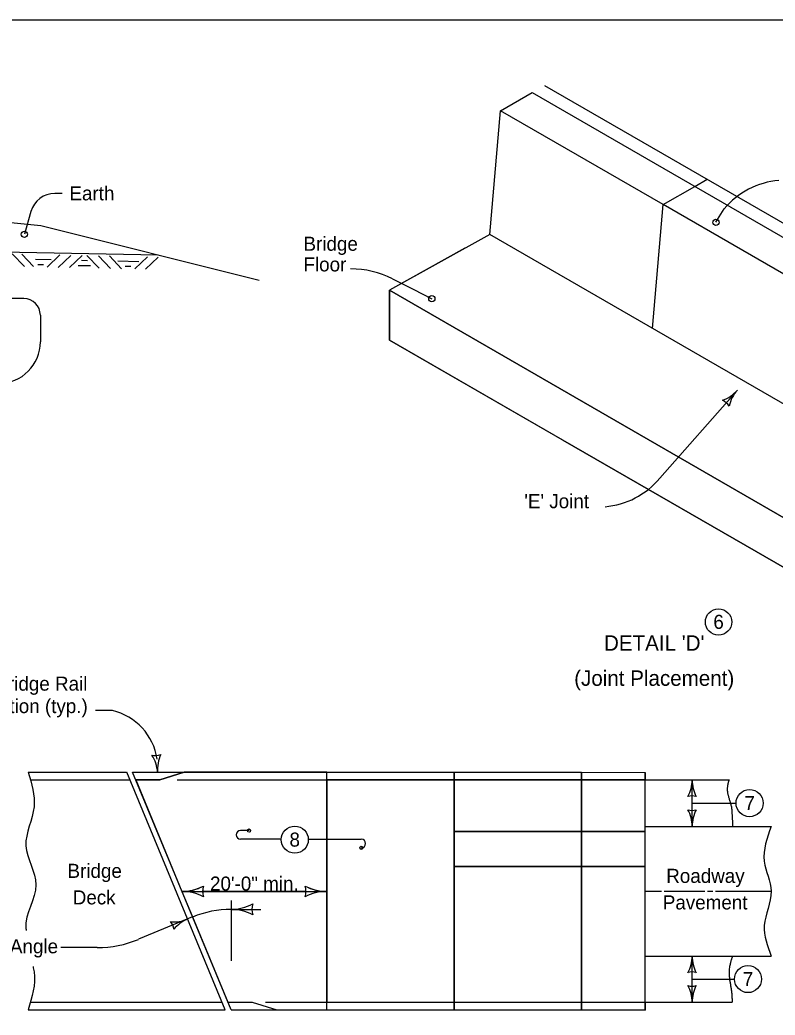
# Model space of a CAD drawing. Extents: x -2134934 to -2124557, y -2139046 to -2134021.
# Drawn here: x -2126647 to -2125788, y -2138168 to -2137036 of the extents above; entities that cross this region are included whole.
import ezdxf

# ---------------------------------------------------------------- set-up
doc = ezdxf.new("R2010")
doc.units = 0
for name, color, linetype in [('BridgeSuperStructureExisting', 7, 'Continuous'), ('dsnAlignmentStation', 7, 'Continuous'), ('dsnCellElements', 7, 'Continuous'), ('dsnStdLabel', 7, 'Continuous'), ('TC_Barrier', 7, 'Continuous')]:
    doc.layers.add(name, color=color, linetype=linetype)

msp = doc.modelspace()

# ---------------------------------------------------------------- linework, layer by layer
at = {"layer": 'BridgeSuperStructureExisting'}
for p, q in [((-2126050, -2137110.4), (-2125548.2, -2137400.1)), ((-2126112.2, -2137280.1), (-2126100, -2137139.2)), ((-2125879.2, -2137225.3), (-2125865, -2137217.2)), ((-2126598.5, -2137233.3), (-2126606.9, -2137233.3)), ((-2126634.2, -2137253.7), (-2126641.7, -2137279.7)), ((-2125927.2, -2137386.9), (-2125915, -2137246)), ((-2125855.1, -2137266.1), (-2125845.8, -2137250.8)), ((-2126735.2, -2137258.5), (-2126622.9, -2137269.7)), ((-2126622.9, -2137269.7), (-2126374.6, -2137331.8)), ((-2126112.2, -2137280.1), (-2126226.3, -2137343.3)), ((-2126112.2, -2137280.1), (-2126226.3, -2137343.3)), ((-2125753.4, -2137487.2), (-2126112.2, -2137280.1)), ((-2125643.5, -2137550.7), (-2126112.2, -2137280.1)), ((-2126140.5, -2137295.7), (-2126226.3, -2137343.3)), ((-2126667.1, -2137299.6), (-2126489.3, -2137303.1)), ((-2126655.4, -2137302.1), (-2126641.5, -2137316.5)), ((-2126644.5, -2137302.4), (-2126631.2, -2137316.4)), ((-2126601.3, -2137303.3), (-2126615.7, -2137317.2)), ((-2126588.9, -2137303.8), (-2126603.3, -2137317.6)), ((-2126575.9, -2137303.8), (-2126590.3, -2137317.7)), ((-2126570.5, -2137303.9), (-2126556.6, -2137318.3)), ((-2126557.5, -2137304.4), (-2126543.6, -2137318.8)), ((-2126545, -2137304.4), (-2126531.2, -2137318.9)), ((-2126501.8, -2137305.3), (-2126516.2, -2137319.2)), ((-2126489.3, -2137305.8), (-2126503.8, -2137319.6)), ((-2126222.9, -2137330.5), (-2126199.6, -2137342.3)), ((-2126226.3, -2137343.3), (-2126226.3, -2137400)), ((-2125775, -2137603.9), (-2126226.3, -2137343.3)), ((-2126226.3, -2137343.3), (-2126226.3, -2137400)), ((-2126226.3, -2137343.3), (-2125775, -2137603.9)), ((-2126226.3, -2137343.3), (-2126029.2, -2137457.2)), ((-2126199.6, -2137342.3), (-2126178.2, -2137353.1)), ((-2126642.4, -2137352.8), (-2126667.1, -2137352.8)), ((-2126623.5, -2137371.7), (-2126623.5, -2137402.1)), ((-2126226.3, -2137400), (-2125757.2, -2137670.8)), ((-2126029.2, -2137513.8), (-2126226.3, -2137400)), ((-2126029.2, -2137457.2), (-2125591.9, -2137709.6)), ((-2125830.6, -2137456.9), (-2125919, -2137557.2)), ((-2126029.2, -2137513.8), (-2125591.9, -2137766.2)), ((-2125591.9, -2137766.2), (-2126029.2, -2137513.8)), ((-2126541.4, -2137821.5), (-2126560.9, -2137821.5)), ((-2126637.5, -2137891.6), (-2126525.4, -2137891.6)), ((-2126413.2, -2138161.9), (-2126525.2, -2137891.6)), ((-2126406.5, -2138161.9), (-2126518.5, -2137891.6)), ((-2126518.5, -2137891.6), (-2126297.8, -2137891.6)), ((-2126459.8, -2137891.6), (-2126487.4, -2137900.3)), ((-2126487.4, -2137900.3), (-2126459.8, -2137891.6)), ((-2126297.8, -2137891.6), (-2126459.8, -2137891.6)), ((-2126297.8, -2137953), (-2126297.8, -2137891.6)), ((-2126297.8, -2138153.1), (-2126297.8, -2137891.6)), ((-2126297.8, -2137891.6), (-2125935.6, -2137891.7)), ((-2126152.9, -2138162), (-2126152.9, -2137891.6)), ((-2126008, -2138162), (-2126008, -2137891.6)), ((-2125935.6, -2138162), (-2125935.6, -2137891.7)), ((-2126634.6, -2137900.3), (-2126521.7, -2137900.3)), ((-2126515, -2137900.3), (-2126487.4, -2137900.3)), ((-2126487.4, -2137900.3), (-2126514.9, -2137900.3)), ((-2126514.9, -2137900.3), (-2126462.4, -2138027.1)), ((-2126467.9, -2137900.3), (-2125840.2, -2137900.3)), ((-2126152.9, -2137900.3), (-2126297.8, -2137900.3)), ((-2125935.6, -2138153.1), (-2125935.6, -2137900.3)), ((-2125882.2, -2137953.1), (-2125882.2, -2137900.3)), ((-2125882.2, -2137926.7), (-2125852.7, -2137926.7)), ((-2125852.7, -2137926.7), (-2125832.2, -2137926.7)), ((-2125935.6, -2137953.1), (-2125792.3, -2137953.1)), ((-2126386.1, -2137957.9), (-2126395.9, -2137957.9)), ((-2126349.4, -2137967.7), (-2126395.9, -2137967.7)), ((-2126318.7, -2137967.7), (-2126258.4, -2137967.7)), ((-2126462.5, -2138027.1), (-2126297.8, -2138027.1)), ((-2126462.4, -2138027.1), (-2126461.8, -2138027.1)), ((-2126438.9, -2138027.1), (-2126321.5, -2138027.1)), ((-2126321.5, -2138027.1), (-2126438.9, -2138027.1)), ((-2126298.6, -2138027.1), (-2126297.8, -2138027.1)), ((-2126297.8, -2138027.1), (-2126297.8, -2138027.1)), ((-2126297.8, -2138027.1), (-2126297.8, -2138095.1)), ((-2126406.5, -2138037.5), (-2126406.5, -2138106.2)), ((-2126450.3, -2138056.2), (-2126511.7, -2138081.6)), ((-2126406.5, -2138047.5), (-2126372.6, -2138047.5)), ((-2126558.8, -2138091), (-2126600.2, -2138091)), ((-2126297.8, -2138095.1), (-2126297.8, -2138153.1)), ((-2126297.8, -2138161.9), (-2126297.8, -2138095.1)), ((-2125935.6, -2138100.6), (-2125792.3, -2138100.6)), ((-2125882.2, -2138153.1), (-2125882.2, -2138100.6)), ((-2125882.2, -2138126.8), (-2125852.7, -2138126.8)), ((-2125852.7, -2138126.8), (-2125834, -2138126.8)), ((-2126634.7, -2138153.1), (-2126416.9, -2138153.1)), ((-2126410.2, -2138153.1), (-2126382.6, -2138153.1)), ((-2126410.2, -2138153.1), (-2126382.6, -2138153.1)), ((-2126382.6, -2138153.1), (-2126354.5, -2138161.9)), ((-2126382.6, -2138153.1), (-2126354.5, -2138161.9)), ((-2126367.5, -2138153.1), (-2125836.6, -2138153.1)), ((-2126297.8, -2138153.1), (-2126247.4, -2138153.1)), ((-2126247.4, -2138153.1), (-2126247.4, -2138153.1)), ((-2126637.5, -2138161.9), (-2126413.2, -2138161.9)), ((-2126406.5, -2138161.9), (-2126297.8, -2138161.9)), ((-2126354.5, -2138161.9), (-2126297.8, -2138161.9)), ((-2126297.8, -2138161.9), (-2125935.6, -2138162))]:
    msp.add_line(p, q, dxfattribs=at)
for points in [[(-2126064.2, -2137118.5), (-2125698.1, -2137329.8), (-2125607.6, -2137382.1), (-2125562.4, -2137408.2), (-2125590.7, -2137424.6), (-2125643.5, -2137402.8), (-2125734, -2137350.5), (-2125915, -2137246), (-2126100, -2137139.2)], [(-2126100, -2137139.2), (-2126064.2, -2137118.5)], [(-2125915, -2137246), (-2125879.2, -2137225.3)], [(-2126629.1, -2137308.2), (-2126611, -2137308.6)], [(-2126576.5, -2137309.3), (-2126570, -2137309.4)], [(-2126535.5, -2137310.1), (-2126511.5, -2137310.6)], [(-2126626.4, -2137314.1), (-2126619.9, -2137314.2)], [(-2126580.5, -2137315.1), (-2126566.3, -2137315.4)], [(-2126526.9, -2137316.1), (-2126520.4, -2137316.2)], [(-2126226.3, -2137400), (-2126226.3, -2137343.3)], [(-2126226.3, -2137400), (-2126226.3, -2137343.3)], [(-2126297.8, -2138027.1), (-2126297.8, -2137967.7), (-2126297.8, -2137953), (-2126297.8, -2137900.3), (-2126297.8, -2137891.6)], [(-2126297.8, -2137900.3), (-2126297.8, -2137967.7), (-2126297.8, -2138027.1)], [(-2126152.9, -2138153.1), (-2126152.9, -2138026.7), (-2126152.9, -2137900.3)], [(-2126462.4, -2138027.1), (-2126450.3, -2138056.2), (-2126410.2, -2138153.1)], [(-2126297.8, -2138161.9), (-2126297.8, -2138153.1), (-2126297.8, -2138100.5), (-2126297.8, -2138027.1)], [(-2126297.8, -2138027.1), (-2126297.8, -2138027.1)], [(-2125935.6, -2138026.8), (-2125916.9, -2138026.8)], [(-2125913.8, -2138026.8), (-2125867.7, -2138026.8)], [(-2125864.7, -2138026.8), (-2125858.5, -2138026.8)], [(-2125855.4, -2138026.8), (-2125792.3, -2138026.8)], [(-2126247.4, -2138153.1), (-2126199.7, -2138153.1), (-2126152.9, -2138153.1)]]:
    msp.add_lwpolyline(points, dxfattribs=at)
for centre, radius in [((-2125852.1, -2137720.7), 15), ((-2125816.8, -2137926.7), 15.4), ((-2126334.1, -2137968.2), 15.4), ((-2126334.1, -2137968.2), 15.4), ((-2125818.6, -2138126.8), 15.4)]:
    msp.add_circle(centre, radius, dxfattribs=at)
for centre, radius, start, end in [((-2125775.9, -2137309.2), 91, 94.8409, 140.1467), ((-2126606.9, -2137261.7), 28.4, 90, 163.739), ((-2126270.6, -2137425), 105.9, 63.2177, 90), ((-2126642.4, -2137371.7), 18.9, 0, 90), ((-2126670.8, -2137402.1), 47.3, 270, 360), ((-2125988.9, -2137498.9), 91, 274.8409, 320.1467), ((-2126556.6, -2137886.4), 66.7, 8.4828, 76.8823), ((-2125922.4, -2137900.3), 40.2, 331.9275, 360), ((-2125842, -2137900.3), 40.2, 180, 208.0725), ((-2125882.2, -2137934), 15.5, 72.2666, 107.7334), ((-2125882.2, -2137919.4), 15.5, 252.2666, 287.7333), ((-2125922.4, -2137953.1), 40.2, 360, 28.0725), ((-2125842, -2137953.1), 40.2, 151.9275, 180), ((-2126395.9, -2137962.8), 4.92, 90, 270), ((-2126258.4, -2137972.7), 4.92, 270, 90), ((-2126462.5, -2137974.9), 52.2, 270, 298.0725), ((-2126462.5, -2137974.9), 52.2, 270.8433, 298.0725), ((-2126418.7, -2138027.1), 20.2, 162.2666, 179.9839), ((-2126418.7, -2138027.1), 20.2, 162.2666, 197.7334), ((-2126341.6, -2138027.1), 20.2, 0.0161, 17.7334), ((-2126297.8, -2137974.9), 52.2, 241.9275, 269.1567), ((-2126341.6, -2138027.1), 20.2, 342.2666, 17.7334), ((-2126297.8, -2137974.9), 52.2, 241.9275, 270), ((-2126462.5, -2138079.4), 52.2, 61.9275, 90), ((-2126462.5, -2138079.4), 52.2, 61.9275, 89.8364), ((-2126418.7, -2138027.1), 20.2, 179.9839, 197.7334), ((-2126297.8, -2138079.4), 52.2, 90.0176, 118.0725), ((-2126341.6, -2138027.1), 20.2, 342.2666, 0.0161), ((-2126297.8, -2138079.4), 52.2, 90, 118.0725), ((-2126297.8, -2137974.9), 52.2, 269.9824, 270), ((-2126406.5, -2137995.3), 52.2, 270, 298.0725), ((-2126406.5, -2137995.3), 52.2, 270, 298.0725), ((-2126362.7, -2138047.5), 20.2, 162.2666, 197.7334), ((-2126362.7, -2138047.5), 20.2, 162.2666, 197.7334), ((-2126406.5, -2138162), 114.5, 90, 112.5), ((-2126406.5, -2138099.7), 52.2, 61.9275, 90), ((-2126406.5, -2138099.7), 52.2, 61.9275, 90), ((-2126471.4, -2138021.5), 40.2, 264.4275, 292.5), ((-2126487.1, -2138071.5), 15.5, 4.7666, 40.2333), ((-2126440.6, -2138095.7), 40.2, 112.5, 140.5725), ((-2126558.8, -2137968.1), 122.9, 270, 292.5), ((-2125922.4, -2138100.6), 40.2, 331.9275, 360), ((-2125842, -2138100.6), 40.2, 180, 208.0725), ((-2125882.2, -2138134.2), 15.5, 72.2666, 107.7334), ((-2125882.2, -2138119.5), 15.5, 252.2666, 287.7333), ((-2125922.4, -2138153.1), 40.2, 360, 28.0725), ((-2125842, -2138153.1), 40.2, 151.9275, 180), ((-2126287.5, -2138153.1), 40.2, 359.9859, 360)]:
    msp.add_arc(centre, radius, start, end, dxfattribs=at)
for points in [[(-2126637.5, -2137891.6), (-2126630.6, -2137930.8), (-2126639.9, -2137975.2), (-2126628.5, -2138019.5), (-2126639.9, -2138069.1), (-2126639.6, -2138071.4)], [(-2125792.3, -2137953.1), (-2125800.1, -2137992.8), (-2125792.3, -2138026.9), (-2125800.1, -2138066), (-2125792.3, -2138100.6)], [(-2126631.8, -2138112.4), (-2126630.6, -2138118.6), (-2126637.5, -2138161.9)]]:
    msp.add_spline(points, degree=3, dxfattribs=at)
for points in [[(-2125840.2, -2137900.3), (-2125840.4, -2137900.8), (-2125840.6, -2137901.3), (-2125840.7, -2137901.8), (-2125840.9, -2137902.3), (-2125841, -2137902.8), (-2125841.2, -2137903.3), (-2125841.4, -2137904.3), (-2125841.6, -2137905.2), (-2125841.8, -2137906.3), (-2125842, -2137907.2), (-2125842.1, -2137908.2), (-2125842.1, -2137909.2), (-2125842.2, -2137909.7), (-2125842.2, -2137910.2), (-2125842.2, -2137910.7), (-2125842.2, -2137911.2), (-2125842.2, -2137911.7), (-2125842.2, -2137912.2), (-2125842.1, -2137913.2), (-2125842, -2137914.1), (-2125841.8, -2137915.1), (-2125841.7, -2137916), (-2125841.5, -2137917), (-2125841.2, -2137917.9), (-2125840.7, -2137919.8), (-2125840.1, -2137921.6), (-2125839.6, -2137923.5), (-2125839, -2137925.4), (-2125838.5, -2137927.3), (-2125837.9, -2137929.2), (-2125837.6, -2137930.1), (-2125837.5, -2137931.1), (-2125837.3, -2137932.1), (-2125837.2, -2137933), (-2125837, -2137934), (-2125837, -2137934.9), (-2125836.9, -2137936.5), (-2125836.8, -2137938), (-2125836.8, -2137939.5), (-2125836.7, -2137941), (-2125836.6, -2137942.5), (-2125836.5, -2137944), (-2125836.4, -2137945.5), (-2125836.4, -2137947), (-2125836.3, -2137948.5), (-2125836.3, -2137950), (-2125836.2, -2137951.5), (-2125836.2, -2137953.1)], [(-2125836.2, -2138100.6), (-2125836.5, -2138101.4), (-2125836.8, -2138102.3), (-2125837.1, -2138103.2), (-2125837.3, -2138104.1), (-2125837.6, -2138104.9), (-2125837.9, -2138105.8), (-2125838.4, -2138107.6), (-2125838.8, -2138109.3), (-2125839.2, -2138111.1), (-2125839.8, -2138113.7), (-2125840.1, -2138116.4), (-2125840.1, -2138119), (-2125840.2, -2138119.5), (-2125840.2, -2138119.9), (-2125840.1, -2138120.4), (-2125840.1, -2138120.8), (-2125840.1, -2138121.3), (-2125840.1, -2138121.7), (-2125840, -2138122.7), (-2125839.9, -2138123.7), (-2125839.8, -2138124.7), (-2125839.7, -2138125.7), (-2125839.6, -2138126.7), (-2125839.5, -2138127.6), (-2125839.2, -2138129.6), (-2125838.8, -2138131.6), (-2125838.5, -2138133.6), (-2125838.2, -2138135.5), (-2125837.9, -2138137.5), (-2125837.6, -2138139.5), (-2125837.4, -2138140.5), (-2125837.3, -2138141.5), (-2125837.2, -2138142.5), (-2125837.1, -2138143.5), (-2125837, -2138144.4), (-2125837, -2138145.4), (-2125836.8, -2138148), (-2125836.7, -2138150.6), (-2125836.6, -2138153.1)]]:
    msp.add_open_spline(points, degree=3, dxfattribs=at)
at = {"layer": 'dsnAlignmentStation'}
msp.add_lwpolyline([(-2127734.4, -2137035.9), (-2124599.4, -2137035.9), (-2124599.4, -2139045.9), (-2127734.4, -2139045.9)], close=True, dxfattribs=at)
at = {"layer": 'dsnCellElements'}
for centre in [(-2126386.1, -2137957.9), (-2126258.4, -2137977.6)]:
    msp.add_circle(centre, 1.78, dxfattribs=at)
for centre, radius, start, end in [((-2125862.5, -2137428.8), 42.5, 290.5435, 318.616), ((-2125798.7, -2137485), 42.5, 138.616, 166.6885), ((-2125854.1, -2137483.6), 16.4, 30.8827, 66.3494), ((-2126492.8, -2137856.1), 16.4, 256.6331, 292.0998), ((-2126532.5, -2137894.8), 42.5, 4.3665, 32.439), ((-2126447.7, -2137888.4), 42.5, 156.294, 184.3665)]:
    msp.add_arc(centre, radius, start, end, dxfattribs=at)
at = {"layer": 'dsnStdLabel'}
for p, q in [((-2126008, -2137900.3), (-2126152.9, -2137900.3)), ((-2126152.9, -2137900.3), (-2126152.9, -2137958.9)), ((-2126008, -2137958.9), (-2126008, -2137900.3)), ((-2125935.6, -2137900.3), (-2126008, -2137900.3)), ((-2126008, -2137900.3), (-2126008, -2137958.9)), ((-2125935.6, -2137958.9), (-2125935.6, -2137900.3)), ((-2126008, -2137958.9), (-2126152.9, -2137958.9)), ((-2126152.9, -2137958.9), (-2126152.9, -2137998.9)), ((-2126152.9, -2137958.9), (-2126008, -2137958.9)), ((-2126008, -2137998.9), (-2126008, -2137958.9)), ((-2126008, -2137958.9), (-2126008, -2137958.9)), ((-2125935.6, -2137958.9), (-2126008, -2137958.9)), ((-2126008, -2137958.9), (-2126008, -2137998.9)), ((-2126008, -2137958.9), (-2125935.6, -2137958.9)), ((-2125935.6, -2137998.9), (-2125935.6, -2137958.9)), ((-2126152.9, -2137998.9), (-2126152.9, -2138153.1)), ((-2126152.9, -2137998.9), (-2126008, -2137998.9)), ((-2126008, -2138153.1), (-2126008, -2137998.9)), ((-2126008, -2137998.9), (-2126008, -2138153.1)), ((-2125935.6, -2137998.9), (-2126008, -2137998.9)), ((-2126008, -2137998.9), (-2125935.6, -2137998.9)), ((-2125935.6, -2138153.1), (-2125935.6, -2137998.9)), ((-2126152.9, -2138153.1), (-2126008, -2138153.1)), ((-2126008, -2138153.1), (-2125935.6, -2138153.1))]:
    msp.add_line(p, q, dxfattribs=at)
for points in [[(-2126297.8, -2137891.6), (-2126152.9, -2137891.6), (-2126152.9, -2137900.3), (-2126272.9, -2137900.3), (-2126297.8, -2137900.3)], [(-2126008, -2137891.6), (-2126008, -2137900.3), (-2126152.9, -2137900.3), (-2126152.9, -2137891.6)], [(-2125935.6, -2137891.7), (-2125935.6, -2137900.3), (-2126008, -2137900.3), (-2126008, -2137891.6)], [(-2126152.9, -2138162), (-2126297.8, -2138161.9), (-2126297.8, -2138153.1), (-2126290.6, -2138153.1), (-2126247.4, -2138153.1), (-2126199.7, -2138153.1), (-2126152.9, -2138153.1)], [(-2126152.9, -2138162), (-2126152.9, -2138153.1), (-2126008, -2138153.1), (-2126008, -2138162)], [(-2125935.6, -2138162), (-2126008, -2138162), (-2126008, -2138153.1), (-2125935.6, -2138153.1)]]:
    msp.add_lwpolyline(points, close=True, dxfattribs=at)
msp.add_lwpolyline([(-2126008, -2137998.9), (-2126008, -2137998.9), (-2126152.9, -2137998.9)], dxfattribs=at)
at = {"layer": 'TC_Barrier'}
for centre in [(-2125855.1, -2137266.1), (-2126641.7, -2137279.7), (-2126178.2, -2137353.1)]:
    msp.add_circle(centre, 3.54, dxfattribs=at)

# ---------------------------------------------------------------- texts
at = {"layer": 'BridgeSuperStructureExisting'}
for s, height, p in [('Bridge', 16, (-2126324.2, -2137298.5)), ('Floor', 16, (-2126324.2, -2137322)), ("'E' Joint", 16, (-2126073, -2137591.3)), ("DETAIL 'D'", 17.5, (-2125982.4, -2137753.3)), ('Bridge Rail', 16, (-2126674.6, -2137798.8)), ('End Section (typ.)', 16, (-2126739.6, -2137824.3))]:
    msp.add_text(s, height=height, dxfattribs=at).set_placement(p)
at = {"layer": 'dsnStdLabel'}
for s, height, p in [('Earth', 16, (-2126590.4, -2137241.2)), ('6', 16, (-2125858, -2137728.5)), ('(Joint Placement)', 17.5, (-2126016.3, -2137793.3)), ('7', 16, (-2125822.7, -2137934.7)), ('8', 16, (-2126340.1, -2137976.2)), ('Bridge', 16, (-2126592.6, -2138011.7)), ('Roadway', 16, (-2125911.6, -2138017.4)), ('20\'-0" min.', 16, (-2126430.5, -2138026.2)), ('Deck', 16, (-2126586.6, -2138041.9)), ('Pavement', 16, (-2125915.5, -2138047.6)), ('Skew Angle', 16, (-2126716.3, -2138097.5)), ('7', 16, (-2125824.5, -2138134.8))]:
    msp.add_text(s, height=height, dxfattribs=at).set_placement(p)

doc.saveas('drawing.dxf')
